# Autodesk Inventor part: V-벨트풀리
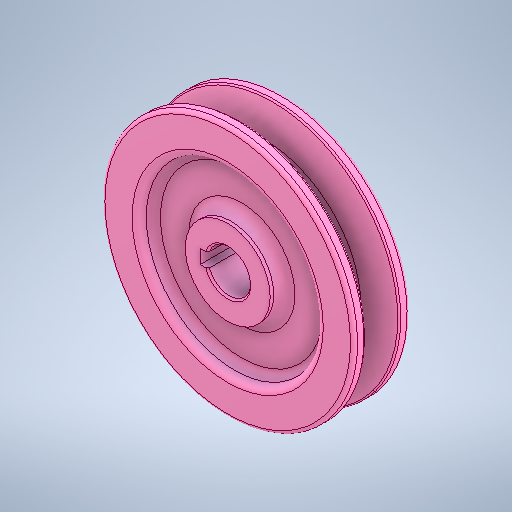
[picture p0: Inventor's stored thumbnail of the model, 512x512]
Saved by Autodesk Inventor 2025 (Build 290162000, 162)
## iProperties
Created: 2024-08
Part Number: V-벨트풀리
Material: 강철, 연강
Document SubType Name: Modeling
Designer: deana
Density: 7.86 g/cm^3
Appearance: 기본값
Author: jhkim
Sending System: Autodesk Inventor 2025
Preprocessor: ST-DEVELOPER v20
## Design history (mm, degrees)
feature "Solid1"
node "솔리드1"
